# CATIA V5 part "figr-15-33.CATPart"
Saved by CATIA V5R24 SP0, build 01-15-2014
Part number: Part1
Bounding box of the stored display mesh (mm): x -40.264 to 42.014, y -25.445 to 25.445, z -51 to 0.75
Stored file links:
  D:\KAVITA\CATIA V5-6R2014 Project_ Kavita\CATIA V5-6R2014_partfiles\Partfiles\c15_catia_v5-6r2014_prt\figr-15-33.CATPart
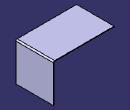
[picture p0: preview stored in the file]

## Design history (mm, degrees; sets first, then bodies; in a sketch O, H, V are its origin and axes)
SheetMetalParameters1: Thickness 0.75, BendRadius 1, KFactor 0.356492 {= log(min(100,max(20*SheetMetalParameters1.BendRadius,SheetMetalParameters1.Thickness)/SheetMetalParameters1.Thickness))/log(100)/2}, ReliefRadialLength 1, ReliefAxialLength 2, MinimumBendRadius 0
Body1 (main body)
  Sketch1 on xy-plane, origin (0, 0, 0), H (1, 0, 0), V (0, 1, 0)
    line L1 (-40.2643, 25.445) -> (40.2643, 25.445)
    line L2 (40.2643, 25.445) -> (40.2643, -25.445)
    line L3 (40.2643, -25.445) -> (-40.2643, -25.445)
    line L4 (-40.2643, -25.445) -> (-40.2643, 25.445)
    horizontal: L1 H, L3 H
    vertical: L2 V, L4 V
    symmetry: L1 L3 H, L4 L2 V
  Wall1: Thickness 0.75, Profile Sketch1
  Flange1: Guide edge [face of Wall1 | face of Wall1], Angle 90, KFacteur 0.356492 {= log(min(100,max(20*Flange1.Radius,SheetMetalParameters1.Thickness)/SheetMetalParameters1.Thickness))/log(100)/2}, Length 50, Radius 1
